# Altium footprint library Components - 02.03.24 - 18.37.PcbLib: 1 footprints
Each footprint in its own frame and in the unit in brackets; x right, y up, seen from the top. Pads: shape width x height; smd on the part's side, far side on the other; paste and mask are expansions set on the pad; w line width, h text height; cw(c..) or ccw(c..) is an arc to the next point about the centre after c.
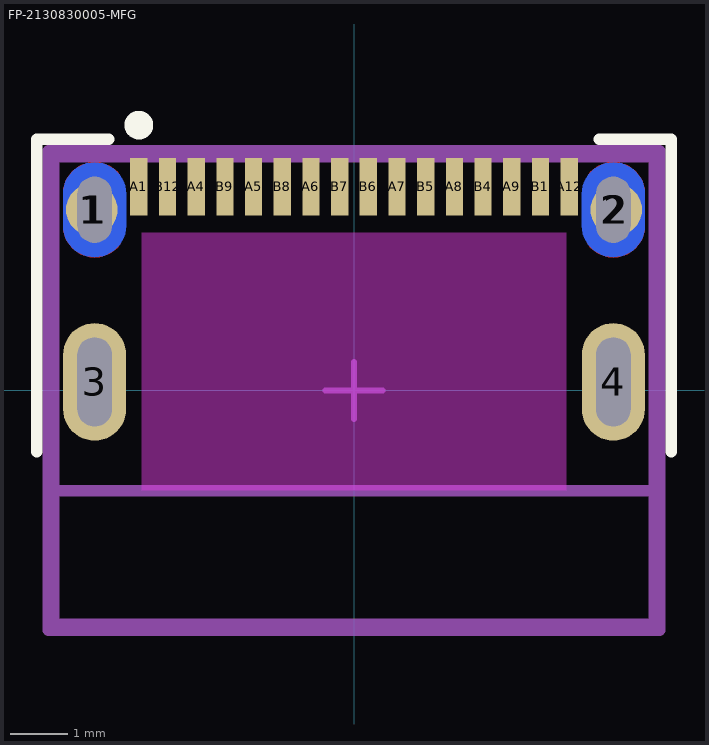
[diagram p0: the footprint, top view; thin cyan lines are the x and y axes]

## FP-2130830005-MFG [mm]
pads (22):
  round 0.9 smd paste-1000 mask+0: 1(-4.57,3.15) 2(4.57,3.15)
  rrect100% 1.1x1.65 smd far side paste-1000 mask+0: 1(-4.52,3.15) 2(4.52,3.15)
  rrect100% 1.1x2.05 hole 1.55 slot 0.6 at 0 deg paste-1000 mask+0: 3(-4.52,0.15) 4(4.52,0.15)
  rect 0.3x1 smd paste+0 mask+0: A1(-3.75,3.55) A4(-2.75,3.55) A5(-1.75,3.55) A6(-0.75,3.55) A7(0.75,3.55) A8(1.75,3.55) A9(2.75,3.55) A12(3.75,3.55) B1(3.25,3.55) B4(2.25,3.55) B5(1.25,3.55) B6(0.25,3.55) B7(-0.25,3.55) B8(-1.25,3.55) B9(-2.25,3.55) B12(-3.25,3.55)
Top Layer:
  region: 5.07,3.425 5.07,3.513 5.015,3.679 4.912,3.821 4.769,3.923 4.602,3.976 4.427,3.974 4.261,3.918 4.12,3.813 4.07,3.741 4.07,2.559 4.12,2.487 4.261,2.382 4.427,2.326 4.602,2.324 4.769,2.377 4.912,2.479 5.015,2.621 5.07,2.787 5.07,2.875
  region: -5.07,3.425 -5.07,3.513 -5.015,3.679 -4.912,3.821 -4.769,3.923 -4.602,3.976 -4.427,3.974 -4.261,3.918 -4.12,3.813 -4.07,3.741 -4.07,2.559 -4.12,2.487 -4.261,2.382 -4.427,2.326 -4.602,2.324 -4.769,2.377 -4.912,2.479 -5.015,2.621 -5.07,2.787 -5.07,2.875
Top Overlay:
  circle w0.25: c-3.75,4.625 r0.125
  lines w0.2: -5.53,-1.07 -5.53,4.375 -4.275,4.375 ; 4.275,4.375 5.53,4.375 5.53,-1.07
Keep-Out Layer:
  rectangle: -3.7,-1.745 3.7,2.755
Top Assembly:
  lines w0.2: -5.33,-4.175 -5.33,4.175 5.33,4.175 5.33,-4.175 -5.33,-4.175
  text ".Designator" at 0,0.188 h1
Top 3D Body:
  lines w0.2: -5.33,-1.745 5.33,-1.745 ; -5.23,-4.075 -5.23,4.075 5.23,4.075 5.23,-4.075 -5.23,-4.075
Top Courtyard:
  lines w0.2: -5.33,-4.175 -5.33,4.175 5.33,4.175 5.33,-4.175 -5.33,-4.175
Top Component Center:
  lines w0.1: -0.5,0 0.5,0 ; 0,-0.5 0,0.5
3D body "Conn_Molex_2130830005_eec.STEP": height 0.25, standoff 0, extent -5.33,-4.175 5.33,4.175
